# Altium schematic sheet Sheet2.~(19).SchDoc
size B; SheetNumber: 1; SheetTotal: 1
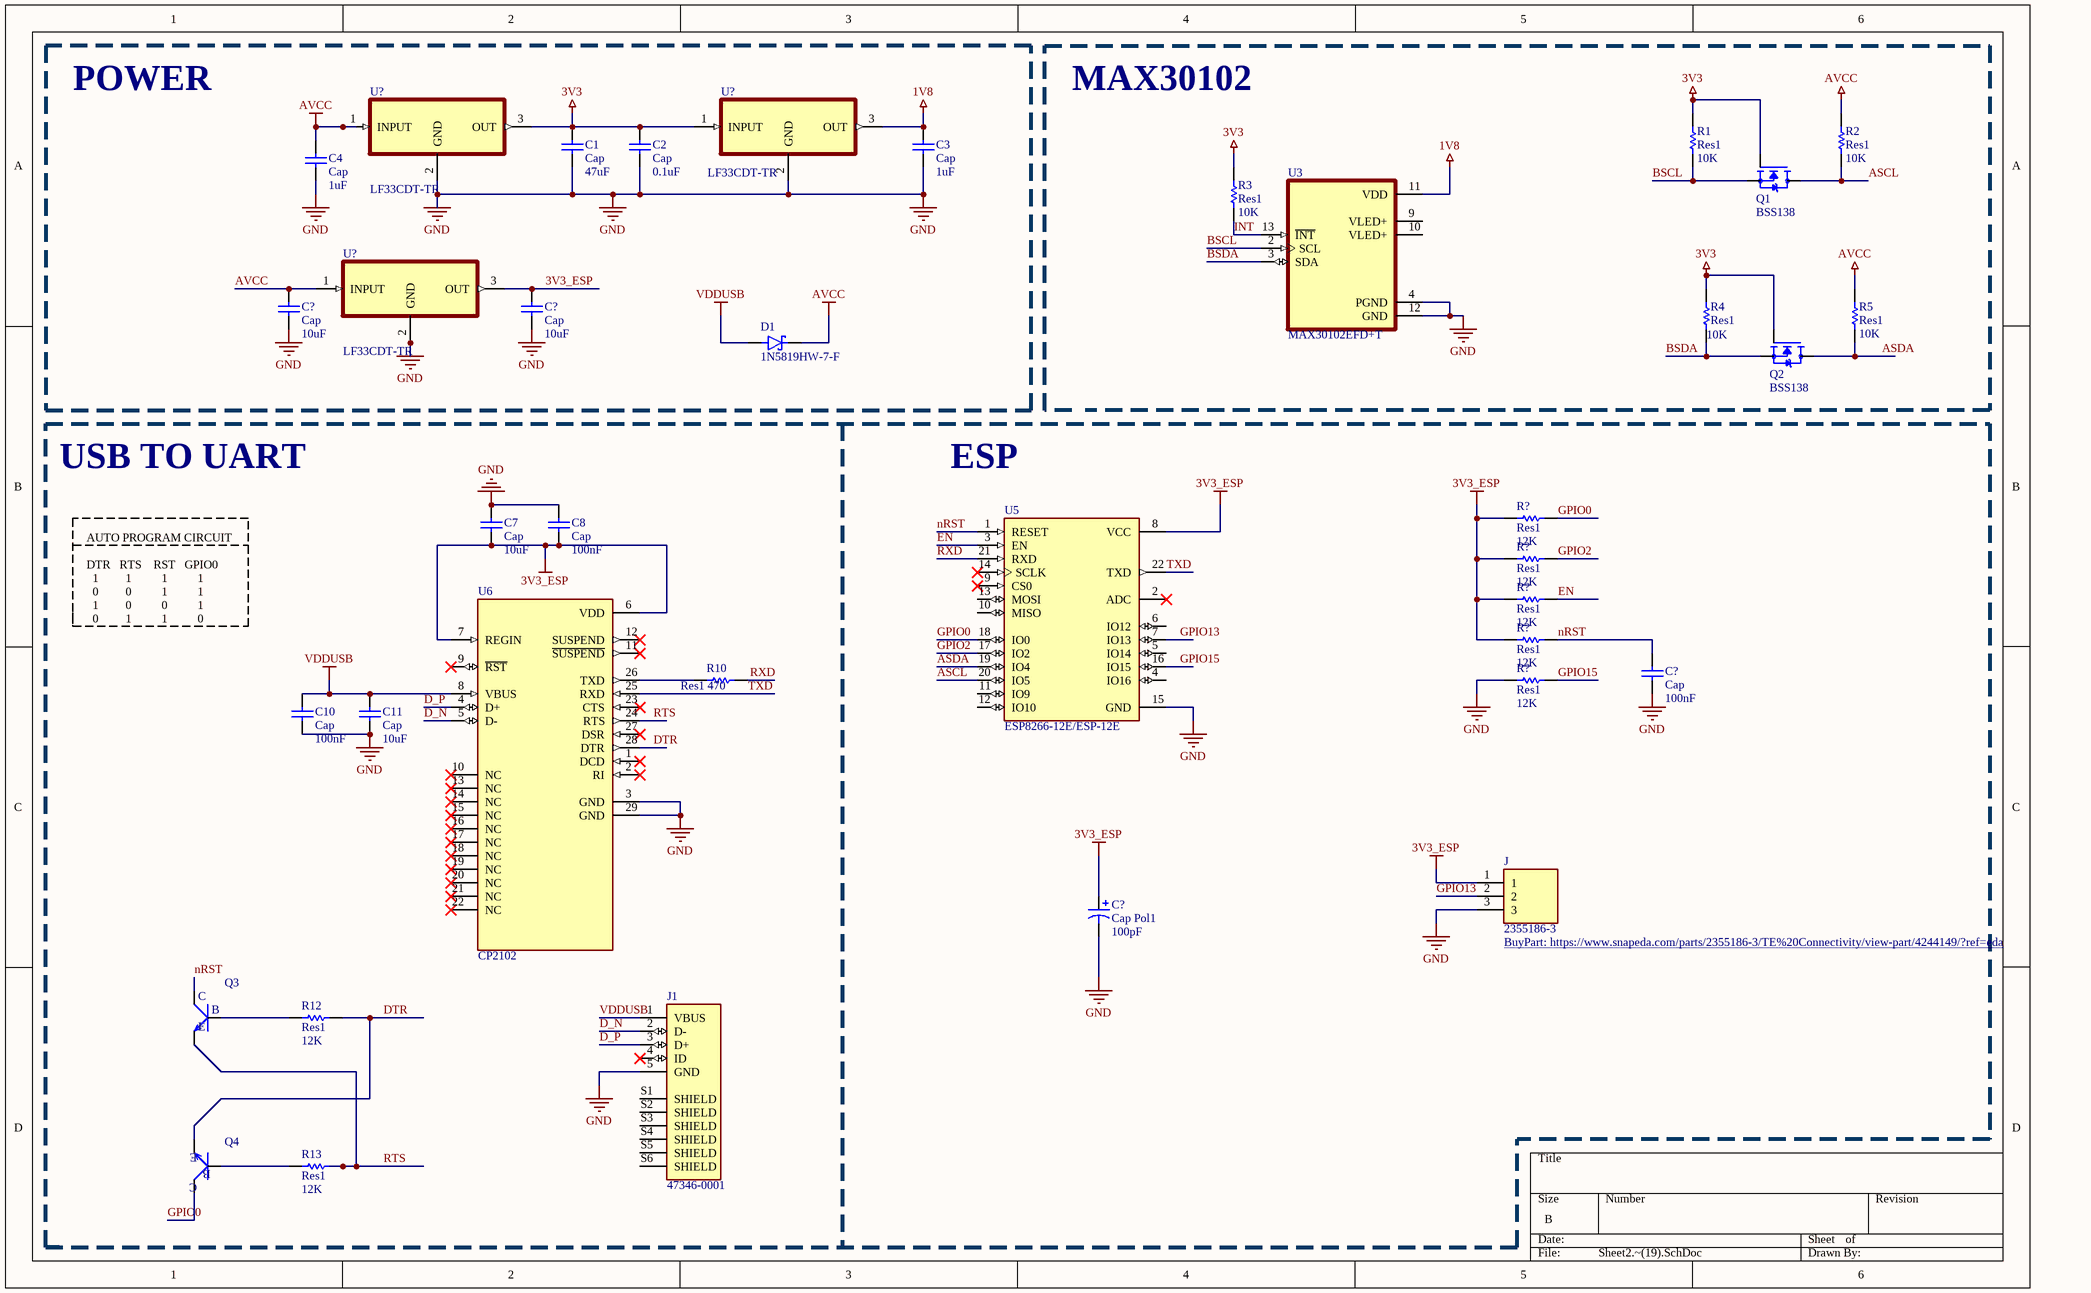
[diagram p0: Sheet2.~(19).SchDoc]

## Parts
(Parts that share a designator on the sheet are numbered #1, #2 ... from top to bottom, then left to right.)
C1  Cap  value 47uF  [RAD-0.3]
C2  Cap  value 0.1uF  [RAD-0.3]
C3  Cap  value 1uF  [RAD-0.3]
C4  Cap  value 1uF  [RAD-0.3]
C7  Cap  value 10uF  [RAD-0.3]
C8  Cap  value 100nF  [RAD-0.3]
C10  Cap  value 100nF  [RAD-0.3]
C11  Cap  value 10uF  [RAD-0.3]
C?#1  Cap  value 10uF  [RAD-0.3]
C?#2  Cap  value 10uF  [RAD-0.3]
C?#3  Cap  value 100nF  [RAD-0.3]
C?#4  Cap Pol1  value 100pF  [RB7.6-15]
D1  1N5819HW-7-F  [SOD3715X145N]
J  2355186-3  [TE_2355186-3]
J1  47346-0001  [MOLEX_47346-0001]
Q1  BSS138  [SOT95P240X111-3N]
Q2  BSS138  [SOT95P240X111-3N]
Q3  SMD-TRANSISTORS-NPN-25V-500MW(SOT-23)  [SOT-23]  (value not drawn)
Q4  SMD-TRANSISTORS-NPN-25V-500MW(SOT-23)  [SOT-23]  (value not drawn)
R1  Res1  value 10K  [AXIAL-0.3]
R2  Res1  value 10K  [AXIAL-0.3]
R3  Res1  value 10K  [AXIAL-0.3]
R4  Res1  value 10K  [AXIAL-0.3]
R5  Res1  value 10K  [AXIAL-0.3]
R10  Res1  value 470  [AXIAL-0.3]
R12  Res1  value 12K  [AXIAL-0.3]
R13  Res1  value 12K  [AXIAL-0.3]
R?#1  Res1  value 12K  [AXIAL-0.3]
R?#2  Res1  value 12K  [AXIAL-0.3]
R?#3  Res1  value 12K  [AXIAL-0.3]
R?#4  Res1  value 12K  [AXIAL-0.3]
R?#5  Res1  value 12K  [AXIAL-0.3]
U3  MAX30102EFD+T  [XDCR_MAX30101EFD+]
U5  ESP8266-12E/ESP-12E  [XCVR_ESP8266-12E/ESP-12E]
U6  CP2102  [QFN50P500X500X100-29N]
U?#1  LF33CDT-TR  [TO228P972X240-3N]
U?#2  LF33CDT-TR  [TO228P972X240-3N]
U?#3  LF33CDT-TR  [TO228P972X240-3N]

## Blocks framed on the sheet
POWER: C1-C4 C?#1 C?#2 D1 U?#1-U?#3

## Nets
1V8: C3.2 U3.11(VDD) U?#2.3(OUT)
3V3: C1.2 C2.2 Q1.1(G) Q2.1(G) R1.2 R3.2 R4.2 U?#1.3(OUT) U?#2.1(INPUT)
3V3_ESP: C7.2 C8.2 C?#2.2 C?#4.1 J.1 R?#1.2 R?#2.2 R?#3.2 R?#4.2 U5.8(VCC) U6.6(VDD) U6.7(REGIN) U?#3.3(OUT)
AVCC: C4.2 C?#1.2 D1.C(K) R2.2 R5.2 U?#1.1(INPUT) U?#3.1(INPUT)
GND: C1.1 C2.1 C3.1 C4.1 C7.1 C8.1 C10.1 C11.1 C?#1.1 C?#2.1 C?#3.1 C?#4.2 J.3 J1.5(GND) R?#5.2 U3.4(PGND) U3.12(GND) U5.15(GND) U6.3(GND) U6.29(GND) U?#1.2(GND) U?#2.2(GND) U?#3.2(GND)
VDDUSB: C10.2 C11.2 D1.A J1.1(VBUS) U6.8(VBUS)
ASCL: Q1.3(D) R2.1 U5.20(IO5)
ASDA: Q2.3(D) R5.1 U5.19(IO4)
BSCL: Q1.2(S) R1.1 U3.2(SCL)
BSDA: Q2.2(S) R4.1 U3.3(SDA)
D_N: J1.2(D-) U6.5(D-)
D_P: J1.3(D+) U6.4(D+)
DTR: Q4.2(E) R12.2 U6.28(DTR)
EN: R?#3.1 U5.3(EN)
GPIO0: Q4.3(C) R?#1.1 U5.18(IO0)
GPIO2: R?#2.1 U5.17(IO2)
GPIO13: J.2 U5.7(IO13)
GPIO15: R?#5.1 U5.16(IO15)
INT: R3.1 U3.13(~{INT})
nRST: C?#3.2 Q3.3(C) R?#4.1 U5.1(RESET)
RTS: Q3.2(E) R13.2 U6.24(RTS)
RXD: R10.2 U5.21(RXD)
TXD: U5.22(TXD) U6.25(RXD)
NetQ3_1: Q3.1(B) R12.1
NetQ4_1: Q4.1(B) R13.1
NetR10_1: R10.1 U6.26(TXD)

Not connected (* = marked no-connect by the designer): J1 4(ID)* S1(SHIELD) S2(SHIELD) S3(SHIELD) S4(SHIELD) S5(SHIELD) S6(SHIELD); U3 9(VLED+) 10(VLED+); U5 2(ADC)* 4(IO16) 5(IO14) 6(IO12) 9(CS0)* 10(MISO) 11(IO9) 12(IO10) 13(MOSI) 14(SCLK)*; U6 1(DCD)* 2(RI)* 9(~{RST})* 10(NC)* 11(~{SUSPEND})* 12(SUSPEND)* 13(NC)* 14(NC)* 15(NC)* 16(NC)* 17(NC)* 18(NC)* 19(NC)* 20(NC)* 21(NC)* 22(NC)* 23(CTS)* 27(DSR)*

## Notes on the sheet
- MAX30102
- USB TO UART
- ESP
- AUTO PROGRAM CIRCUIT
  DTR   RTS    RST   GPIO0
  1         1          1          1
  0         0          1          1
  1         0          0          1
  0         1          1          0

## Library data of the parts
C1-C4 C7 C8 C10 C11 C?#1-C?#3 = Cap: Capacitor
C?#4 = Cap Pol1: Polarized Capacitor (Radial)
D1 = 1N5819HW-7-F: Diode Schottky 40 V 1A Surface Mount SOD-123; MF: Diodes Inc.
J = 2355186-3: Pin 3P,2MM,BRK HDR,SRVT,2.8,0.76AU,BOX 3 POS; MF: TE Connectivity
J1 = 47346-0001: USB - micro B USB 2.0 Receptacle Connector 5 Position Surface Mount, Right Angle; MF: Molex
Q1 Q2 = BSS138: N-Channel 50 V 220mA (Ta) 350mW (Ta) Surface Mount SOT-23-3; MF: onsemi
Q3 Q4 = SMD-TRANSISTORS-NPN-25V-500MW(SOT-23): Bipolar (BJT) Transistor NPN 25 V 500 mA 150MHz 300 mW Surface Mount SOT-23; MF: UMW; MP: S8050
R1-R5 R10 R12 R13 R?#1-R?#5 = Res1: Resistor
U3 = MAX30102EFD+T: Pulse Oximeter and Heart Rate Sensor Digital Output; MF: Maxim Integrated Products
U5 = ESP8266-12E/ESP-12E: This WiFi module has a 32-bit MCU micro and clock speeds supporting 80 MHz or 160 MHz. Supports the RTOS and integrated Wi-Fi MAC/BB/RF/PA/LNA, and has an on-board antenna.; MF: AI-Thinker
U6 = CP2102: CP2102N USB 2.0 to UART (RS232) Bridge Interface Evaluation Board; MF: Silicon Labs
U?#1-U?#3 = LF33CDT-TR: Linear Voltage Regulator IC Positive Fixed 1 Output 500mA DPAK; MF: STMicroelectronics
